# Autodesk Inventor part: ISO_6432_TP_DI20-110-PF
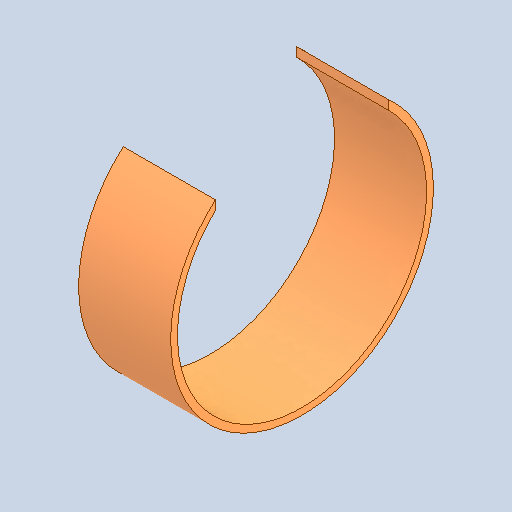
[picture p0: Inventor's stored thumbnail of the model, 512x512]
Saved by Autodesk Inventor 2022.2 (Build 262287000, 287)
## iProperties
Created: 2024-10
Part Number: ISO_6432_TP_DI20-110-PF
Material: Generico
Document SubType Name: Modeling
Designer: 18907419
Density: 1 g/cm^3
Appearance: Default
Author: 18907419
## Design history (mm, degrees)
feature "Solid1"
node "Solido1"
